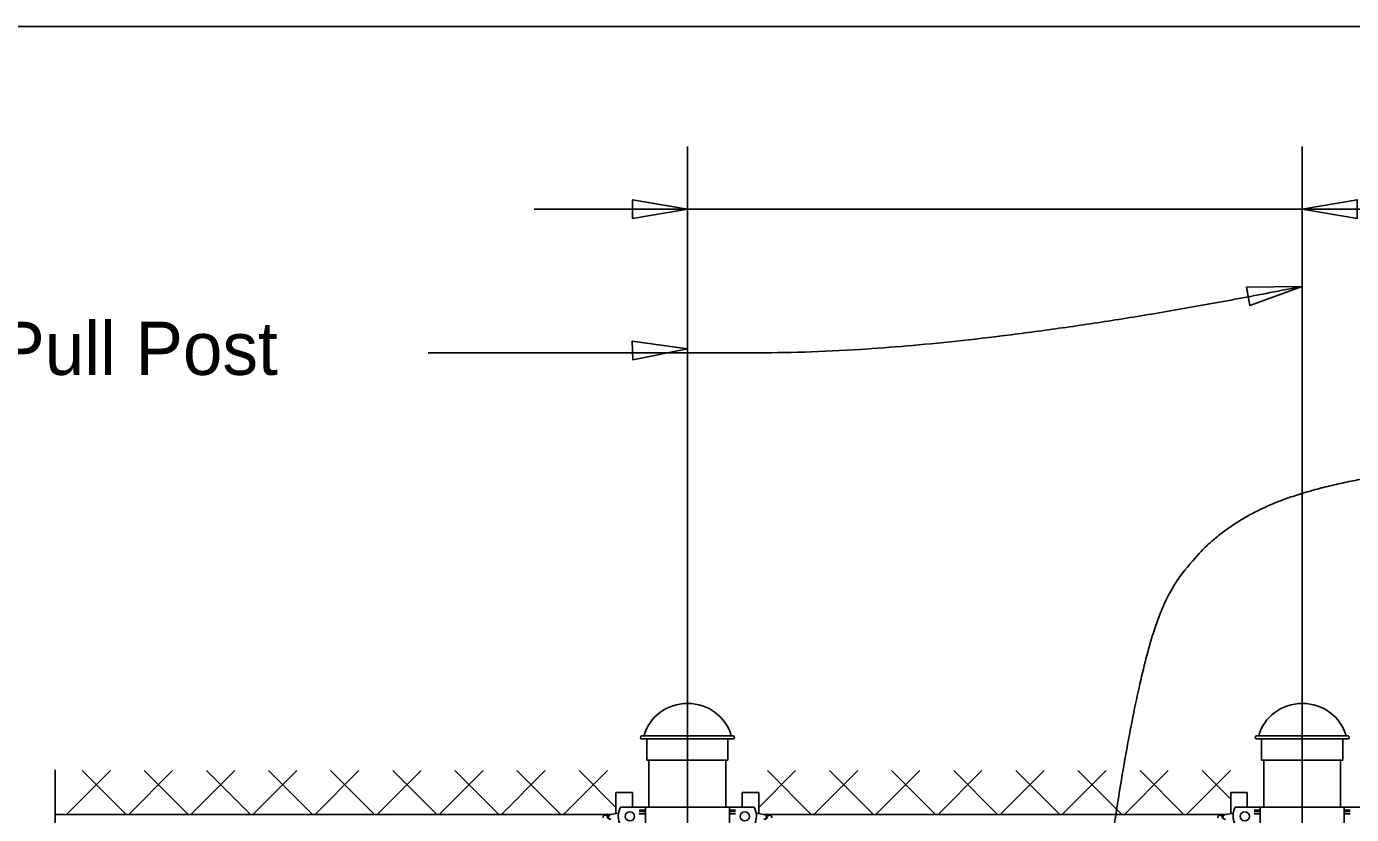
# Model space of a CAD drawing. Extents: x 0 to 41.2, y 0 to 26.
# Drawn here: x 23.73 to 28.76, y 22.97 to 25.96 of the extents above; entities that cross this region are included whole.
import ezdxf

# ---------------------------------------------------------------- set-up
doc = ezdxf.new("R2010")
doc.units = 0
for name, color, linetype in [('ActivePts-ConstElements', 7, 'Continuous'), ('CL_Major', 7, 'Continuous'), ('Dimension', 7, 'Continuous'), ('Miscellaneous', 7, 'Continuous'), ('Miscellaneous1', 7, 'Continuous'), ('SteelMisc', 7, 'Continuous'), ('TextStructures', 7, 'Continuous')]:
    doc.layers.add(name, color=color, linetype=linetype)

msp = doc.modelspace()

# ---------------------------------------------------------------- linework, layer by layer
at = {"layer": 'ActivePts-ConstElements'}
msp.add_lwpolyline([(0, 0), (41.2106, 0), (41.2106, 25.96), (0, 25.96)], close=True, dxfattribs=at)
at = {"layer": 'CL_Major'}
for p, q in [((26.2429, 25.5043), (26.2429, 12.3953)), ((28.5763, 25.5043), (28.5763, 13.5039))]:
    msp.add_line(p, q, dxfattribs=at)
at = {"layer": 'Dimension'}
msp.add_line((25.6609, 25.2672), (34.1233, 25.2672), dxfattribs=at)
for points in [[(26.2429, 25.2672), (26.0347, 25.3025), (26.0347, 25.2319)], [(28.5762, 25.2672), (28.7845, 25.2319), (28.7845, 25.3025)], [(28.5762, 24.9738), (28.3651, 24.9702), (28.378, 24.9009)], [(26.2429, 24.737), (26.0337, 24.766), (26.0358, 24.6954)]]:
    msp.add_lwpolyline(points, close=True, dxfattribs=at)
msp.add_lwpolyline([(23.8431, 23.1382), (23.8431, 21.1819), (23.9465, 21.1819), (23.8431, 21.1369), (23.7398, 21.0919), (23.8431, 21.0919), (23.8431, 20.1983)], dxfattribs=at)
for points in [[(25.2588, 24.7214), (25.7125, 24.7214), (27.3088, 24.7214), (28.5763, 24.9737)], [(29.3712, 24.2725), (28.9427, 24.2977), (28.2117, 24.0791), (27.9092, 23.4903), (27.7412, 21.9834)]]:
    msp.add_open_spline(points, degree=2, dxfattribs=at)
at = {"layer": 'Miscellaneous'}
for p, q in [((24.0538, 23.1361), (23.8871, 22.9695)), ((24.113, 22.9695), (23.9463, 23.1361)), ((24.2895, 23.1361), (24.1228, 22.9695)), ((24.3487, 22.9695), (24.182, 23.1361)), ((24.5252, 23.1361), (24.3585, 22.9695)), ((24.5844, 22.9695), (24.4177, 23.1361)), ((24.7609, 23.1361), (24.5942, 22.9695)), ((24.8201, 22.9695), (24.6534, 23.1361)), ((24.9966, 23.1361), (24.8299, 22.9695)), ((25.0558, 22.9695), (24.8891, 23.1361)), ((25.2323, 23.1361), (25.0656, 22.9695)), ((25.2915, 22.9695), (25.1248, 23.1361)), ((25.468, 23.1361), (25.3013, 22.9695)), ((25.5272, 22.9695), (25.3605, 23.1361)), ((25.7037, 23.1361), (25.537, 22.9695)), ((25.7629, 22.9695), (25.5962, 23.1361)), ((25.9394, 23.1361), (25.7727, 22.9695)), ((25.972, 22.996), (25.8319, 23.1361)), ((26.5138, 22.996), (26.6539, 23.1361)), ((26.5465, 23.1361), (26.7131, 22.9695)), ((26.7229, 22.9695), (26.8896, 23.1361)), ((26.7822, 23.1361), (26.9488, 22.9695)), ((26.9586, 22.9695), (27.1253, 23.1361)), ((27.0179, 23.1361), (27.1845, 22.9695)), ((27.1943, 22.9695), (27.361, 23.1361)), ((27.2536, 23.1361), (27.4202, 22.9695)), ((27.4301, 22.9695), (27.5967, 23.1361)), ((27.4893, 23.1361), (27.6559, 22.9695)), ((27.6658, 22.9695), (27.8324, 23.1361)), ((27.725, 23.1361), (27.8916, 22.9695)), ((27.9015, 22.9695), (28.0681, 23.1361)), ((27.9607, 23.1361), (28.1273, 22.9695)), ((28.1372, 22.9695), (28.3038, 23.1361)), ((28.1964, 23.1361), (28.3054, 23.0271))]:
    msp.add_line(p, q, dxfattribs=at)
at = {"layer": 'Miscellaneous1'}
msp.add_lwpolyline([(0, 25.96), (41.2106, 25.96), (41.2106, 0), (0, 0)], close=True, dxfattribs=at)
at = {"layer": 'SteelMisc'}
for p, q in [((26.0707, 23.2681), (26.4153, 23.2681)), ((26.4153, 23.2559), (26.0707, 23.2559)), ((26.0889, 23.1761), (26.0889, 23.2559)), ((26.397, 23.1761), (26.397, 23.2559)), ((28.404, 23.2681), (28.7486, 23.2681)), ((28.7486, 23.2559), (28.404, 23.2559)), ((28.4222, 23.1761), (28.4222, 23.2559)), ((28.7304, 23.1761), (28.7304, 23.2559)), ((26.397, 23.1761), (26.0889, 23.1761)), ((26.0971, 22.9966), (26.0971, 23.1761)), ((26.3888, 22.9966), (26.3888, 23.1761)), ((28.7304, 23.1761), (28.4222, 23.1761)), ((28.4305, 22.9966), (28.4305, 23.1761)), ((28.7221, 22.9966), (28.7221, 23.1761)), ((25.972, 22.9726), (25.972, 23.0528)), ((26.0345, 23.0528), (25.972, 23.0528)), ((26.0345, 22.9966), (26.0345, 23.0528)), ((26.4513, 22.9966), (26.4513, 23.0528)), ((26.4513, 23.0528), (26.5138, 23.0528)), ((26.4513, 22.9966), (26.4513, 23.0528)), ((26.4513, 23.0528), (26.5138, 23.0528)), ((26.5138, 22.9726), (26.5138, 23.0528)), ((26.5138, 22.9726), (26.5138, 23.0528)), ((28.3054, 22.9726), (28.3054, 23.0528)), ((28.3679, 23.0528), (28.3054, 23.0528)), ((28.3679, 22.9966), (28.3679, 23.0528)), ((26.3988, 22.9966), (25.989, 22.9966)), ((26.0604, 22.9858), (26.0834, 22.9858)), ((26.0834, 22.9289), (26.0834, 22.9966)), ((26.0872, 22.9966), (26.4969, 22.9966)), ((26.4254, 22.9858), (26.4024, 22.9858)), ((26.4026, 22.9289), (26.4026, 22.9966)), ((28.7321, 22.9966), (28.3223, 22.9966)), ((28.3937, 22.9858), (28.4167, 22.9858)), ((28.4167, 22.9289), (28.4167, 22.9966)), ((28.4206, 22.9966), (28.8303, 22.9966)), ((28.7588, 22.9858), (28.7358, 22.9858)), ((28.7359, 22.9289), (28.7359, 22.9966)), ((25.9337, 22.9695), (23.8431, 22.9695)), ((25.9817, 22.9741), (25.9524, 22.9695)), ((26.0604, 22.9802), (26.0834, 22.9802)), ((26.0604, 22.9722), (26.0834, 22.9722)), ((26.4254, 22.9802), (26.4024, 22.9802)), ((26.4254, 22.9722), (26.4024, 22.9722)), ((26.5042, 22.9741), (26.5335, 22.9695)), ((26.5043, 22.9741), (26.5336, 22.9695)), ((26.5522, 22.9695), (28.267, 22.9695)), ((28.3151, 22.9741), (28.2858, 22.9695)), ((28.3937, 22.9802), (28.4167, 22.9802)), ((28.3937, 22.9722), (28.4167, 22.9722)), ((28.7588, 22.9802), (28.7358, 22.9802)), ((28.7588, 22.9722), (28.7358, 22.9722))]:
    msp.add_line(p, q, dxfattribs=at)
for centre, start, end in [((26.0708, 23.2618), 91.1647, 268.8353), ((26.4151, 23.2618), 271.1647, 88.8353), ((28.4041, 23.2618), 91.1647, 268.8353), ((28.7484, 23.2618), 271.1647, 88.8353)]:
    msp.add_arc(centre, 0.00613, start, end, dxfattribs=at)
for centre, major_axis, ratio, start_param, end_param in [((26.2436, 23.227), (0.1711, 0), 0.957868, 0.252602, 2.888574), ((28.5769, 23.227), (0.1711, 0), 0.957868, 0.252602, 2.888574), ((26.0582, 22.963), (-0.0776, 0), 0.957868, 5.81433, 6.762456), ((26.4276, 22.963), (0.0776, 0), 0.957868, 5.803915, 6.752041), ((26.4276, 22.963), (0.0776, 0), 0.957868, 5.803915, 6.752041), ((28.3916, 22.963), (-0.0776, 0), 0.957868, 5.81433, 6.762456), ((25.9368, 22.9562), (0.0142, 0), 0.957868, 1.486836, 3.141593), ((25.9415, 22.9617), (0.00872, 0), 0.957868, 1.29026, 2.959852), ((25.9481, 22.9612), (0.00872, 0), 0.957868, 1.29026, 4.182385), ((25.9538, 22.9604), (-0.0115, -0.0041), 0.737732, 4.35367, 7.47816), ((26.5321, 22.9604), (0.0115, -0.0041), 0.737732, 5.08821, 8.212701), ((26.5321, 22.9604), (0.0115, -0.0041), 0.737732, 5.08821, 8.212701), ((26.5377, 22.9612), (-0.00872, 0), 0.957868, 2.1008, 4.992926), ((26.5377, 22.9612), (-0.00872, 0), 0.957868, 2.1008, 4.992926), ((26.5443, 22.9617), (-0.00872, 0), 0.957868, 3.323334, 4.992926), ((26.5443, 22.9617), (-0.00872, 0), 0.957868, 3.323334, 4.992926), ((26.549, 22.9562), (-0.0142, 0), 0.957868, 3.141593, 4.79635), ((26.549, 22.9562), (-0.0142, 0), 0.957868, 3.141593, 4.79635), ((28.2701, 22.9562), (0.0142, 0), 0.957868, 1.486836, 3.141593), ((28.2749, 22.9617), (0.00872, 0), 0.957868, 1.29026, 2.959852), ((28.2814, 22.9612), (0.00872, 0), 0.957868, 1.29026, 4.182385), ((28.2871, 22.9604), (-0.0115, -0.0041), 0.737732, 4.35367, 7.47816)]:
    msp.add_ellipse(centre, major_axis=major_axis, ratio=ratio, start_param=start_param, end_param=end_param, dxfattribs=at)
for centre, major_axis in [((26.0249, 22.9621), (0.0178, 0)), ((26.4609, 22.9621), (-0.0178, 0)), ((26.4609, 22.9621), (-0.0178, 0)), ((28.3582, 22.9621), (0.0178, 0))]:
    msp.add_ellipse(centre, major_axis=major_axis, ratio=0.957868, dxfattribs=at)

# ---------------------------------------------------------------- texts
at = {"layer": 'TextStructures'}
msp.add_text('℄ Pull Post', height=0.2016, dxfattribs=at).set_placement((23.4401, 24.6377))

doc.saveas('drawing.dxf')
